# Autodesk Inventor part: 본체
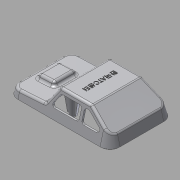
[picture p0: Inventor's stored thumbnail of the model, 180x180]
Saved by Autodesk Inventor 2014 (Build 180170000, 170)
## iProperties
Created: 2015-05
Part Number: 본체
Material: ABS 플라스틱
Document SubType Name: Modeling
Designer: Administrator
Density: 1.06 g/cm^3
Appearance: 매끄러움 - 흰색
Mass: 33.3276 g
Surface Area: 311.374 cm^2
Volume: 31.4411 cm^3
Author: Administrator
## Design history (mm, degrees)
sketch "스케치6"
  geometry: L1 (-49, -38)-(49, -38); L2 (61, -26)-(61, 26); L3 (49, 38)-(-49, 38); L4 (-61, 26)-(-61, -26); L5 (-61, -38)-(61, 38); L6 (61, -38)-(-61, 38); A1 r 12 centre (-49, 26) between (-49, 38) and (-61, 26); A2 r 12 centre (-49, -26) between (-61, -26) and (-49, -38); A3 r 12 centre (49, -26) between (49, -38) and (61, -26); A4 r 12 centre (49, 26) between (61, 26) and (49, 38); 1 further point
  constraints: 12 end point, 8 point on circle, 8 point on line, 8 tangent, 4 centre point, 3 equal radius, 2 midpoint, 2 parallel, 1 horizontal, 1 perpendicular
  dimensions: "d15" = 122 distance of L6.end L5.end; "d16" = 76 distance of L5.end L6.start; "d17" = 12 radius of A1
extrude "돌출4" new body sketch "스케치6" distance "d18" = 30; taper "d19" = -15 deg
sketch "스케치7"
  geometry: L1 (-31, 30)-(-61, 30); L2 (-61, 30)-(-61, 10); L3 (-61, 10)-(-31, 30); L4 (49, 30)-(-49, 30) reference; 3 further points
  constraints: 6 end point, 1 collinear, 1 horizontal, 1 midpoint, 1 perpendicular, 1 vertical alignment
  dimensions: "d20" = 20 vertical distance of L1.start L2.end; "d21" = 30 horizontal distance of L1.start L2.end
extrude "돌출5" cut sketch "스케치7" stored distance "d22" = 30; taper "d23" = 0 deg
sketch "스케치8"
  geometry: L1 (6.558, 30)-(19, 10.089); L2 (19, 10.089)-(58.856, 8); L3 (61, 0)-(52.962, 30) reference; L4 (49, 30)-(-31, 30) reference; L5 (-49, 0)-(49, 0) reference; L6 (61, 0)-(49, 0) reference; L7 (49, 30)-(52.962, 30) reference; 1 further point
  constraints: 4 end point, 2 point on line
  dimensions: "d24" = 8 vertical distance of L3.start L2.end; "d25" = 42 horizontal distance of L3.start L1.end; "d26" = 125 deg angle of L2 L1; "d27" = 3 deg angle of L5 L2
extrude "돌출6" cut sketch "스케치8" stored distance "d28" = 30; taper "d29" = 0 deg
sketch "스케치9"
  geometry: L1 (-39.911, 9.297)-(-39.911, 61.297) reference; L2 (-31.47, 48.297)-(-11.47, 48.297); L3 (-11.47, 48.297)-(-11.47, 22.297); L4 (-11.47, 22.297)-(-31.47, 22.297); L5 (-31.47, 22.297)-(-31.47, 48.297); L6 (-42.47, 61.297)-(-42.47, 9.297) reference; 3 further points
  constraints: 8 end point, 2 midpoint, 2 parallel, 1 horizontal, 1 horizontal alignment, 1 perpendicular
  dimensions: "d30" = 11 distance between parallel lines of L6 L5; "d31" = 20 distance of L2.start L2.end; "d32" = 26 distance of L2.end L3.end
extrude "돌출7" join sketch "스케치9" distance "d33" = 5; taper "d34" = 0 deg
fillet "모깎기1" dims "d35" = 3
fillet "모깎기2" dims "d36" = 3
fillet "모깎기3" dims "d37" = 3
fillet "모깎기4" dims "d38" = 3
feature "쉘1" dims "d39" = 2
node "작업 평면1"
sketch "스케치10"
  geometry: A1 r 4 centre (21, 0) between (25, 0) and (17, 0); A2 r 4 centre (10, 0) between (14, 0) and (6, 0); A3 r 4 centre (-10, 0) between (-6, 0) and (-14, 0); A4 r 4 centre (-21, 0) between (-17, 0) and (-25, 0); 3 further points
  constraints: 8 point on circle, 4 centre point, 13 other
  dimensions: "d41" = 8 diameter of A1; "d42" = 8 diameter of A2; "d43" = 8 diameter of A3; "d44" = 8 diameter of A4; "d45" = 10 distance of A3.centre point (0, 0); "d46" = 20 distance of A2.centre A3.centre; "d47" = 11 distance of A1.centre A2.centre; "d48" = 11 distance of A3.centre A4.centre
extrude "돌출8" join sketch "스케치10" stored distance "d49" = 5; taper "d50" = 0 deg
chamfer "모따기1" distance "d51" = 1; stored, may be unused: second distance "d52" = 2, angle "d53" = 45 deg
sketch "스케치11"
  geometry: L1 (4.895, 30)-(-30.092, 30) reference; L2 (18.172, 11.413)-(7.439, 28.59) reference; L3 (-31.756, 29.496)-(-50.664, 16.891) reference; L4 (2.124, 25)-(-17.84, 25); L5 (10.292, 14.59)-(4.668, 23.59); L6 (7.747, 10)-(-17.84, 10); L7 (-20.84, 13)-(-20.84, 22); L8 (-30.242, 24.496)-(-43.742, 15.496); L9 (-42.078, 10)-(-26.986, 10); L10 (-23.986, 13)-(-23.986, 22); L11 (-26.986, 25)-(-28.578, 25); A1 r 3 centre (7.747, 13) between (7.747, 10) and (10.292, 14.59); A2 r 3 centre (2.124, 22) between (4.668, 23.59) and (2.124, 25); A3 r 3 centre (-17.84, 22) between (-17.84, 25) and (-20.84, 22); A4 r 3 centre (-17.84, 13) between (-20.84, 13) and (-17.84, 10); A5 r 3 centre (-26.986, 22) between (-23.986, 22) and (-26.986, 25); A6 r 3 centre (-28.578, 22) between (-28.578, 25) and (-30.242, 24.496); A7 r 3 centre (-42.078, 13) between (-43.742, 15.496) and (-42.078, 10); A8 r 3 centre (-26.986, 13) between (-26.986, 10) and (-23.986, 13); 7 further points
  constraints: 16 end point, 16 point on circle, 16 tangent, 12 point on line, 8 centre point, 6 equal radius, 5 parallel, 3 perpendicular
  dimensions: "d54" = 5 distance between parallel lines of L2 L5; "d55" = 5 distance between parallel lines of L1 L4; "d56" = 34 distance of point (13.16, 10) point (-20.84, 10); "d57" = 15 distance of point (-20.84, 10) point (-20.84, 25); "d58" = 3 radius of A1; "d59" = 5 distance between parallel lines of L3 L8; "d60" = 5 distance between parallel lines of L1 L11; "d61" = 15 distance of point (-23.986, 10) point (-23.986, 25); "d62" = 28 distance of point (-51.986, 10) point (-23.986, 10); "d63" = 3 radius of A5
extrude "돌출9" cut sketch "스케치11" stored distance "d64" = 5; taper "d65" = 0 deg
sketch "스케치12"
  geometry: L1 (58.929, 26)-(58.929, -26) reference; L2 (49, -35.929)-(-49, -35.929) reference; L3 (-58.929, -26)-(-58.929, 26) reference; L4 (-49, 35.929)-(49, 35.929) reference; L5 (49, 36.929)-(-49, 36.929); L6 (-59.929, 26)-(-59.929, -26); L7 (-49, -36.929)-(49, -36.929); L8 (59.929, -26)-(59.929, 26); A1 r 9.929 centre (49, -26) between (49, -35.929) and (58.929, -26) reference; A2 r 9.929 centre (-49, -26) between (-58.929, -26) and (-49, -35.929) reference; A3 r 9.929 centre (-49, 26) between (-49, 35.929) and (-58.929, 26) reference; A4 r 9.929 centre (49, 26) between (58.929, 26) and (49, 35.929) reference; A5 r 10.929 centre (-49, 26) between (-49, 36.929) and (-59.929, 26); A6 r 10.929 centre (-49, -26) between (-59.929, -26) and (-49, -36.929); A7 r 10.929 centre (49, -26) between (49, -36.929) and (59.929, -26); A8 r 10.929 centre (49, 26) between (59.929, 26) and (49, 36.929); 1 further point
  constraints: 8 end point, 8 point on circle, 4 centre point, 7 other
  dimensions: "d66" = 1 distance between parallel lines of L5 L4
extrude "돌출10" join sketch "스케치12" distance "d67" = 1; taper "d68" = 0 deg
sketch "스케치13"
  geometry: C1 r 3 at (40, 0); C2 r 3 at (0, -22); C3 r 3 at (0, 22); C4 r 3 at (-40, 0); 1 further point
  constraints: 4 centre point, 2 horizontal alignment, 2 vertical alignment
  dimensions: "d69" = 6 diameter of C1; "d70" = 6 diameter of C2; "d71" = 6 diameter of C3; "d72" = 6 diameter of C4; "d73" = 22 distance of C2.centre point (0, 0); "d74" = 44 distance of C2.centre C3.centre; "d75" = 40 distance of point (0, 0) C1.centre; "d76" = 40 distance of point (0, 0) C4.centre
extrude "돌출11" join sketch "스케치13" stored distance "d77" = 1; taper "d78" = 4 deg
node "작업 평면2"
sketch "스케치18"
  geometry: L1 (-45, 1)-(-35, 1); L2 (-35, 1)-(-35, -1); L3 (-35, -1)-(-45, -1); L4 (-45, -1)-(-45, 1); L5 (-45, 1)-(-35, -1); L6 (-35, 1)-(-45, -1); L7 (-5, 23)-(5, 23); L8 (5, 23)-(5, 21); L9 (5, 21)-(-5, 21); L10 (-5, 21)-(-5, 23); L11 (-5, 23)-(5, 21); L12 (5, 23)-(-5, 21); L13 (-5, -21)-(5, -21); L14 (5, -21)-(5, -23); L15 (5, -23)-(-5, -23); L16 (-5, -23)-(-5, -21); L17 (-5, -21)-(5, -23); L18 (5, -21)-(-5, -23); L19 (35, 1)-(45, 1); L20 (45, 1)-(45, -1); L21 (45, -1)-(35, -1); L22 (35, -1)-(35, 1); L23 (35, 1)-(45, -1); L24 (45, 1)-(35, -1); C1 r 3 at (0, 22) reference; C2 r 3 at (-40, 0) reference; C3 r 3 at (0, -22) reference; C4 r 3 at (40, 0) reference; 1 further point
  constraints: 48 end point, 8 midpoint, 8 parallel, 4 horizontal, 4 perpendicular
  dimensions: "d101" = 10 distance of L2.end L3.end; "d102" = 2 distance of L1.end L2.end; "d103" = 10 distance of L8.end L9.end; "d104" = 2 distance of L7.end L8.end; "d105" = 10 distance of L14.end L15.end; "d106" = 2 distance of L13.end L14.end; "d107" = 10 distance of L20.end L21.end; "d108" = 2 distance of L19.end L20.end
extrude "돌출15" join sketch "스케치18" stored distance "d109" = 2; taper "d110" = 2.5 deg
sketch "스케치19"
  geometry: L1 (1.498, 26.025)-(3.159, 26.025) reference; L2 (2.024, 0)-(0, 0) reference; L3 (2.024, 0)-(3.159, 26.025) reference; L4 (2.024, 0)-(6.613, 26.025); L5 (6.613, 26.025)-(1.498, 26.025); 1 further point
  constraints: 4 end point, 1 collinear, 1 other
  dimensions: "d111" = 80 deg angle of L5 L4
extrude "돌출16" join sketch "스케치19" stored distance "d112" = 2; taper "d113" = 0 deg
sketch "스케치20"
  geometry: L1 (-1.09, 24.998)-(-0.743, 25.554) reference; L2 (0, 0)-(-1.09, 24.998) reference; L3 (0, 0)-(-3.677, 20.854); L4 (-1.09, 24.998)-(-3.677, 20.854); L5 (35.092, 24.902)-(0.105, 24.902) reference; 1 further point
  constraints: 4 end point, 1 collinear
  dimensions: "d114" = 80 deg angle of L5 L3
extrude "돌출17" join sketch "스케치20" stored distance "d115" = 2; taper "d116" = 0 deg
sketch "스케치21"
  geometry: L1 (0.984, 16.972)-(2.714, 15.818) reference; L2 (2.024, 0)-(2.714, 15.818) reference; L3 (2.024, 0)-(4.592, 14.565); L4 (2.714, 15.818)-(4.592, 14.565); L5 (-12.885, 23.943)-(-47.872, 23.943) reference; 1 further point
  constraints: 4 end point, 1 collinear
  dimensions: "d117" = 80 deg angle of L5 L3
extrude "돌출18" join sketch "스케치21" stored distance "d118" = 2; taper "d119" = 0 deg
sketch "스케치22"
  geometry: L1 (-1.031, 23.64)-(0.727, 22.466) reference; L2 (0, 0)-(-1.031, 23.64) reference; L3 (0, 0)-(-4.587, 26.012); L4 (-1.031, 23.64)-(-4.587, 26.012); L5 (-39.895, 26.723)-(-4.908, 26.723) reference; 1 further point
  constraints: 4 end point, 1 collinear
  dimensions: "d120" = 80 deg angle of L5 L3
extrude "돌출19" join sketch "스케치22" stored distance "d121" = 2; taper "d122" = 0 deg
sketch "스케치23"
  geometry: L1 (2.472, -10.288)-(0.594, -10.189) reference; L2 (2.024, 0)-(2.472, -10.288) reference; L3 (0, 0)-(2.024, 0) reference; L4 (2.024, 0)-(3.286, -10.288); L5 (2.472, -10.288)-(3.286, -10.288); 1 further point
  constraints: 4 end point, 1 parallel
  dimensions: "d123" = 80 deg angle of L1 L4
extrude "돌출20" join sketch "스케치23" stored distance "d124" = 2; taper "d125" = 0 deg
sketch "스케치24"
  geometry: L1 (0, 0)-(-0.424, -9.717) reference; L2 (0, 0)-(-2.137, -9.643); L3 (-0.424, -9.717)-(-2.137, -9.643); 1 further point
  constraints: 4 end point, 1 perpendicular
  dimensions: "d126" = 80 deg angle of L3 L2
extrude "돌출21" join sketch "스케치24" stored distance "d127" = 2; taper "d128" = 0 deg
hole "구멍1" diameter "d131" = 3.242; stored, may be unused: countersink angle "d135" = 90 deg, drill point angle "d137" = 118 deg; dims "d129" = 10, "d130" = 10, "d132" = 9, "d133" = 4, "d134" = 2, "d136" = 11
hole "구멍2" diameter "d140" = 3.242; stored, may be unused: countersink angle "d144" = 90 deg, drill point angle "d146" = 118 deg; dims "d138" = 10, "d139" = 10, "d141" = 9, "d142" = 4, "d143" = 2, "d145" = 11
hole "구멍3" diameter "d149" = 3.242; stored, may be unused: countersink angle "d153" = 90 deg, drill point angle "d155" = 118 deg; dims "d147" = 10, "d148" = 10, "d150" = 9, "d151" = 4, "d152" = 2, "d154" = 11
hole "구멍4" diameter "d158" = 3.242; stored, may be unused: countersink angle "d162" = 90 deg, drill point angle "d164" = 118 deg; dims "d156" = 10, "d157" = 10, "d159" = 9, "d160" = 4, "d161" = 2, "d163" = 11
sketch "스케치26"
  geometry: L1 (61, -26)-(61, 26) reference; 2 further points
  constraints: 1 other
  dimensions: "d169" = 50 distance from line of L1 point (11, -0.09)
feature "엠보싱2" sketch "스케치26" dims "d15" = 122, "d16" = 76, "d17" = 12, "d167" = 0.5, "d168" = 0
node "솔리드3"
mirror "대칭2"
node "투영된 루프4"
node "투영된 루프5"
node "투영된 루프6"
node "투영된 루프7"
other parameters: "d40" = -63, "d79" = 2
